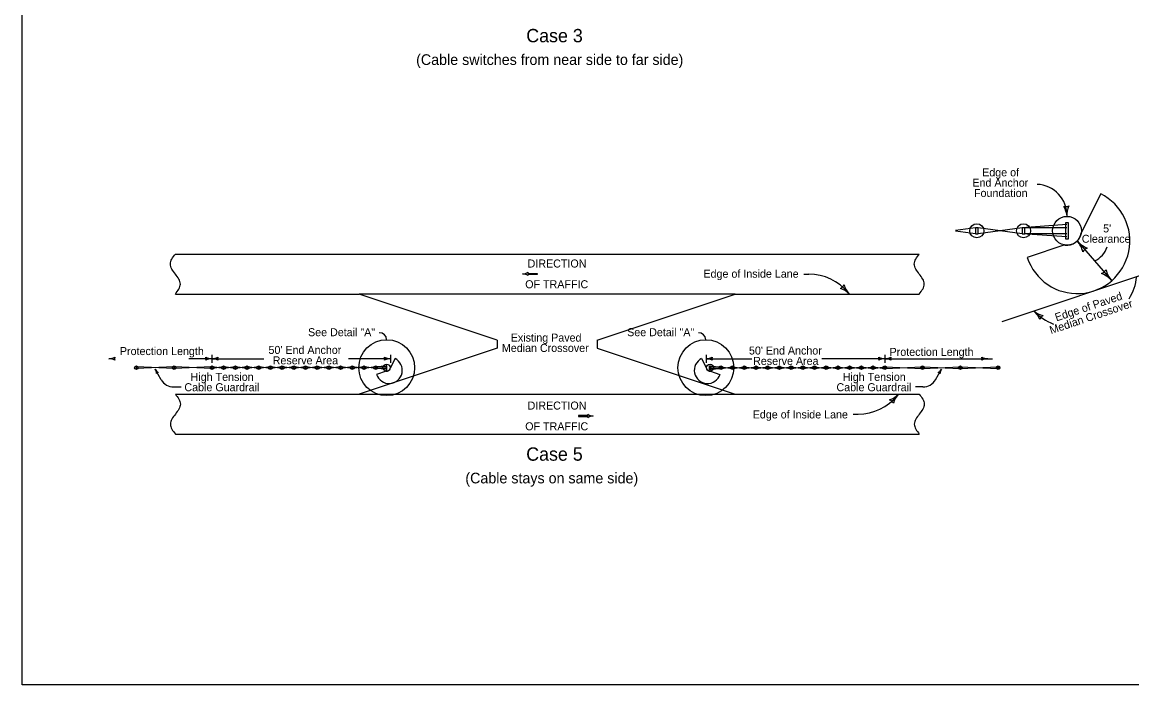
# Model space of a CAD drawing. Extents: x 10133 to 81668, y 7924 to 11018.
# Drawn here: x 10133 to 11797, y 7924 to 8918 of the extents above; entities that cross this region are included whole.
import ezdxf

# ---------------------------------------------------------------- set-up
doc = ezdxf.new("R2010")
doc.units = 0
for name, color, linetype in [('dsnCellElements', 7, 'Continuous'), ('DsnShtRevisedText', 7, 'Continuous'), ('dsnStdDimension', 7, 'Continuous'), ('Level 8', 7, 'Continuous'), ('SheetBorder', 7, 'Continuous')]:
    doc.layers.add(name, color=color, linetype=linetype)

msp = doc.modelspace()

# ---------------------------------------------------------------- linework, layer by layer
at = {"layer": 'dsnCellElements'}
for p, q in [((11562.3, 8609.3), (11532.3, 8605.3)), ((11562.3, 8600.3), (11532.3, 8604.4)), ((11632.4, 8609.3), (11566.1, 8600.3)), ((11632.4, 8600.3), (11566.1, 8609.3)), ((11699.4, 8614.1), (11632.4, 8609.3)), ((11699.4, 8609.3), (11636.1, 8609.3)), ((11699.4, 8595.6), (11632.4, 8600.3)), ((11699.4, 8600.3), (11636.1, 8600.3)), ((10359.9, 8400.6), (10304.1, 8398.3)), ((10359.9, 8398.3), (10304.1, 8400.6)), ((10416.6, 8400.6), (10360.8, 8398.3)), ((10416.6, 8398.3), (10360.8, 8400.6)), ((10434.2, 8400.6), (10417.5, 8398.3)), ((10434.2, 8398.3), (10417.5, 8400.6)), ((10451.7, 8400.6), (10435.1, 8398.3)), ((10451.7, 8398.3), (10435.1, 8400.6)), ((10469.3, 8400.6), (10452.6, 8398.3)), ((10469.3, 8398.3), (10452.6, 8400.6)), ((10486.8, 8400.6), (10470.2, 8398.3)), ((10486.8, 8398.3), (10470.2, 8400.6)), ((10504.3, 8400.6), (10487.7, 8398.3)), ((10504.3, 8398.3), (10487.7, 8400.6)), ((10521.9, 8400.6), (10505.3, 8398.3)), ((10521.9, 8398.3), (10505.3, 8400.6)), ((10539.4, 8400.6), (10522.8, 8398.3)), ((10539.4, 8398.3), (10522.8, 8400.6)), ((10557, 8398.3), (10540.4, 8400.6)), ((10557, 8400.6), (10540.4, 8398.3)), ((10574.5, 8400.6), (10557.9, 8398.3)), ((10574.5, 8398.3), (10557.9, 8400.6)), ((10592, 8400.6), (10575.5, 8398.3)), ((10592, 8398.3), (10575.5, 8400.6)), ((10609.6, 8400.6), (10593, 8398.3)), ((10609.6, 8398.3), (10593, 8400.6)), ((10627.2, 8400.6), (10610.6, 8398.3)), ((10627.2, 8398.3), (10610.6, 8400.6)), ((10644.7, 8400.6), (10628.1, 8398.3)), ((10644.7, 8398.3), (10628.1, 8400.6)), ((10662.3, 8400.6), (10645.7, 8398.3)), ((10662.3, 8398.3), (10645.7, 8400.6)), ((10679, 8401.8), (10662.3, 8400.6)), ((10679, 8397.2), (10662.3, 8398.3)), ((10679, 8400.6), (10663.2, 8400.6)), ((10679, 8398.3), (10663.2, 8398.3)), ((11164.1, 8401.8), (11180.9, 8400.6)), ((11164.1, 8400.6), (11179.9, 8400.6)), ((11164.1, 8398.3), (11179.9, 8398.3)), ((11164.1, 8397.2), (11180.9, 8398.3)), ((11180.9, 8400.6), (11197.5, 8398.3)), ((11180.9, 8398.3), (11197.5, 8400.6)), ((11198.4, 8400.6), (11215, 8398.3)), ((11198.4, 8398.3), (11215, 8400.6)), ((11216, 8400.6), (11232.6, 8398.3)), ((11216, 8398.3), (11232.6, 8400.6)), ((11233.5, 8400.6), (11250.1, 8398.3)), ((11233.5, 8398.3), (11250.1, 8400.6)), ((11251.1, 8400.6), (11267.7, 8398.3)), ((11251.1, 8398.3), (11267.7, 8400.6)), ((11268.6, 8400.6), (11285.2, 8398.3)), ((11268.6, 8398.3), (11285.2, 8400.6)), ((11286.2, 8398.3), (11302.8, 8400.6)), ((11286.2, 8400.6), (11302.8, 8398.3)), ((11303.7, 8400.6), (11320.3, 8398.3)), ((11303.7, 8398.3), (11320.3, 8400.6)), ((11321.3, 8400.6), (11337.8, 8398.3)), ((11321.3, 8398.3), (11337.8, 8400.6)), ((11338.8, 8400.6), (11355.4, 8398.3)), ((11338.8, 8398.3), (11355.4, 8400.6)), ((11356.3, 8400.6), (11372.9, 8398.3)), ((11356.3, 8398.3), (11372.9, 8400.6)), ((11373.9, 8400.6), (11390.5, 8398.3)), ((11373.9, 8398.3), (11390.5, 8400.6)), ((11391.4, 8400.6), (11408, 8398.3)), ((11391.4, 8398.3), (11408, 8400.6)), ((11409, 8400.6), (11425.6, 8398.3)), ((11409, 8398.3), (11425.6, 8400.6)), ((11426.5, 8400.6), (11482.3, 8398.3)), ((11426.5, 8398.3), (11482.3, 8400.6)), ((11483.2, 8400.6), (11539, 8398.3)), ((11483.2, 8398.3), (11539, 8400.6)), ((11539.9, 8400.6), (11595.7, 8398.3)), ((11539.9, 8398.3), (11595.7, 8400.6))]:
    msp.add_line(p, q, dxfattribs=at)
for points in [[(11566.1, 8600.3), (11566.1, 8609.3), (11562.3, 8609.3), (11562.3, 8600.3)], [(11636.2, 8600.3), (11636.2, 8609.3), (11632.4, 8609.3), (11632.4, 8600.3)], [(11701.9, 8592.8), (11701.9, 8616.9), (11697, 8616.9), (11697, 8592.8)], [(10304.1, 8398.3), (10304.1, 8400.6), (10303.2, 8400.6), (10303.2, 8398.3)], [(10360.8, 8398.3), (10360.8, 8400.6), (10359.9, 8400.6), (10359.9, 8398.3)], [(10360.8, 8398.3), (10360.8, 8400.6), (10359.9, 8400.6), (10359.9, 8398.3)], [(10417.5, 8398.3), (10417.5, 8400.6), (10416.6, 8400.6), (10416.6, 8398.3)], [(10417.5, 8398.3), (10417.5, 8400.6), (10416.6, 8400.6), (10416.6, 8398.3)], [(10435.1, 8398.3), (10435.1, 8400.6), (10434.2, 8400.6), (10434.2, 8398.3)], [(10452.6, 8398.3), (10452.6, 8400.6), (10451.7, 8400.6), (10451.7, 8398.3)], [(10470.2, 8398.3), (10470.2, 8400.6), (10469.3, 8400.6), (10469.3, 8398.3)], [(10487.7, 8398.3), (10487.7, 8400.6), (10486.8, 8400.6), (10486.8, 8398.3)], [(10505.3, 8398.3), (10505.3, 8400.6), (10504.3, 8400.6), (10504.3, 8398.3)], [(10522.8, 8398.3), (10522.8, 8400.6), (10521.9, 8400.6), (10521.9, 8398.3)], [(10540.4, 8398.3), (10540.4, 8400.6), (10539.4, 8400.6), (10539.4, 8398.3)], [(10557.9, 8398.3), (10557.9, 8400.6), (10557, 8400.6), (10557, 8398.3)], [(10575.5, 8398.3), (10575.5, 8400.6), (10574.5, 8400.6), (10574.5, 8398.3)], [(10593, 8398.3), (10593, 8400.6), (10592, 8400.6), (10592, 8398.3)], [(10610.6, 8398.3), (10610.6, 8400.6), (10609.6, 8400.6), (10609.6, 8398.3)], [(10628.1, 8398.3), (10628.1, 8400.6), (10627.2, 8400.6), (10627.2, 8398.3)], [(10645.7, 8398.3), (10645.7, 8400.6), (10644.7, 8400.6), (10644.7, 8398.3)], [(10663.2, 8398.3), (10663.2, 8400.6), (10662.3, 8400.6), (10662.3, 8398.3)], [(10679.6, 8396.5), (10679.6, 8402.5), (10678.4, 8402.5), (10678.4, 8396.5)], [(11163.5, 8396.5), (11163.5, 8402.5), (11164.7, 8402.5), (11164.7, 8396.5)], [(11179.9, 8398.3), (11179.9, 8400.6), (11180.9, 8400.6), (11180.9, 8398.3)], [(11197.5, 8398.3), (11197.5, 8400.6), (11198.4, 8400.6), (11198.4, 8398.3)], [(11215, 8398.3), (11215, 8400.6), (11216, 8400.6), (11216, 8398.3)], [(11232.6, 8398.3), (11232.6, 8400.6), (11233.5, 8400.6), (11233.5, 8398.3)], [(11250.1, 8398.3), (11250.1, 8400.6), (11251.1, 8400.6), (11251.1, 8398.3)], [(11267.7, 8398.3), (11267.7, 8400.6), (11268.6, 8400.6), (11268.6, 8398.3)], [(11285.2, 8398.3), (11285.2, 8400.6), (11286.2, 8400.6), (11286.2, 8398.3)], [(11302.8, 8398.3), (11302.8, 8400.6), (11303.7, 8400.6), (11303.7, 8398.3)], [(11320.3, 8398.3), (11320.3, 8400.6), (11321.3, 8400.6), (11321.3, 8398.3)], [(11337.8, 8398.3), (11337.8, 8400.6), (11338.8, 8400.6), (11338.8, 8398.3)], [(11355.4, 8398.3), (11355.4, 8400.6), (11356.3, 8400.6), (11356.3, 8398.3)], [(11372.9, 8398.3), (11372.9, 8400.6), (11373.9, 8400.6), (11373.9, 8398.3)], [(11390.5, 8398.3), (11390.5, 8400.6), (11391.4, 8400.6), (11391.4, 8398.3)], [(11408, 8398.3), (11408, 8400.6), (11409, 8400.6), (11409, 8398.3)], [(11425.6, 8398.3), (11425.6, 8400.6), (11426.5, 8400.6), (11426.5, 8398.3)], [(11425.6, 8398.3), (11425.6, 8400.6), (11426.5, 8400.6), (11426.5, 8398.3)], [(11482.3, 8398.3), (11482.3, 8400.6), (11483.2, 8400.6), (11483.2, 8398.3)], [(11482.3, 8398.3), (11482.3, 8400.6), (11483.2, 8400.6), (11483.2, 8398.3)], [(11539, 8398.3), (11539, 8400.6), (11539.9, 8400.6), (11539.9, 8398.3)], [(11539, 8398.3), (11539, 8400.6), (11539.9, 8400.6), (11539.9, 8398.3)], [(11595.7, 8398.3), (11595.7, 8400.6), (11596.6, 8400.6), (11596.6, 8398.3)]]:
    msp.add_lwpolyline(points, close=True, dxfattribs=at)
for centre, radius in [((11699.4, 8604.8), 21.6), ((11564.2, 8604.8), 10.6), ((11634.3, 8604.8), 10.6), ((10679, 8399.5), 5.4), ((11164.1, 8399.5), 5.4), ((10303.7, 8399.5), 2.66), ((10360.4, 8399.5), 2.66), ((10360.4, 8399.5), 2.66), ((10417.1, 8399.5), 2.66), ((10417.1, 8399.5), 2.66), ((10434.6, 8399.5), 2.66), ((10452.2, 8399.5), 2.66), ((10469.7, 8399.5), 2.66), ((10487.2, 8399.5), 2.66), ((10504.8, 8399.5), 2.66), ((10522.3, 8399.5), 2.66), ((10539.9, 8399.5), 2.66), ((10557.4, 8399.5), 2.66), ((10575, 8399.5), 2.66), ((10592.5, 8399.5), 2.66), ((10610.1, 8399.5), 2.66), ((10627.6, 8399.5), 2.66), ((10645.2, 8399.5), 2.66), ((10662.7, 8399.5), 2.66), ((11180.4, 8399.5), 2.66), ((11197.9, 8399.5), 2.66), ((11215.5, 8399.5), 2.66), ((11233, 8399.5), 2.66), ((11250.6, 8399.5), 2.66), ((11268.1, 8399.5), 2.66), ((11285.7, 8399.5), 2.66), ((11303.2, 8399.5), 2.66), ((11320.8, 8399.5), 2.66), ((11338.3, 8399.5), 2.66), ((11355.9, 8399.5), 2.66), ((11373.4, 8399.5), 2.66), ((11391, 8399.5), 2.66), ((11408.5, 8399.5), 2.66), ((11426.1, 8399.5), 2.66), ((11426.1, 8399.5), 2.66), ((11482.8, 8399.5), 2.66), ((11482.8, 8399.5), 2.66), ((11539.5, 8399.5), 2.66), ((11539.5, 8399.5), 2.66), ((11596.2, 8399.5), 2.66)]:
    msp.add_circle(centre, radius, dxfattribs=at)
at = {"layer": 'DsnShtRevisedText'}
for p, q in [((11750.1, 8660.3), (11720.8, 8601.8)), ((11750.1, 8660.3), (11720.8, 8601.8)), ((11714.7, 8589.6), (11766.5, 8529.9)), ((11696.4, 8583.5), (11639.7, 8564.6)), ((11696.4, 8583.5), (11639.7, 8564.6)), ((11602.1, 8468.7), (11860.1, 8554.7)), ((10883, 8540.1), (10883, 8540.1)), ((10891, 8542.6), (10891, 8540.8)), ((10891, 8540.8), (10905, 8540.8)), ((10905, 8539.3), (10891, 8539.3)), ((10891, 8539.3), (10891, 8537.5)), ((10905, 8540.8), (10905, 8539.3)), ((11304.7, 8539.7), (11312.2, 8539.7)), ((10417, 8413), (10382.5, 8413)), ((10417, 8419), (10417, 8407)), ((10417, 8413), (10494.9, 8413)), ((10685.1, 8413), (10621.7, 8413)), ((10691.7, 8413.3), (10684.4, 8398.7)), ((10691.7, 8413.3), (10684.4, 8398.7)), ((10685.1, 8419), (10685.1, 8407)), ((11151.5, 8413.3), (11158.8, 8398.7)), ((11151.5, 8413.3), (11158.8, 8398.7)), ((11158.1, 8419), (11158.1, 8407)), ((11158.1, 8413), (11226.8, 8413)), ((11426.2, 8413), (11331.8, 8413)), ((11426.2, 8419), (11426.2, 8407)), ((11426.2, 8413), (11535.6, 8413)), ((11535.6, 8413), (11587.9, 8413)), ((10340.9, 8381.5), (10332, 8397.1)), ((10678.2, 8394.1), (10664.1, 8389.4)), ((10678.2, 8394.1), (10664.1, 8389.4)), ((11164.9, 8394.1), (11179, 8389.4)), ((11164.9, 8394.1), (11179, 8389.4)), ((11502.2, 8381.5), (11511.1, 8397.1)), ((10359.7, 8370.6), (10371, 8370.6)), ((11483.4, 8370.6), (11472.1, 8370.6)), ((10980.9, 8327.8), (10966.9, 8327.8)), ((10966.9, 8327.8), (10966.9, 8326.3)), ((10966.9, 8326.3), (10980.9, 8326.3)), ((10980.9, 8329.6), (10980.9, 8327.8)), ((10980.9, 8326.3), (10980.9, 8324.5)), ((10989, 8327.1), (10989, 8327.1)), ((11378.6, 8330), (11386.1, 8330))]:
    msp.add_line(p, q, dxfattribs=at)
for centre in [(10679.2, 8399.5), (11157.8, 8399.5)]:
    msp.add_circle(centre, 41.9, dxfattribs=at)
for centre, radius, start, end in [((11653, 8627.9), 46.5, 358.2185, 88.2185), ((11714.7, 8589.6), 79, 198.4349, 63.4349), ((11714.7, 8589.6), 79, 198.4349, 63.4349), ((11697.3, 8653.5), 12.5, 256.782, 292.2487), ((11667.2, 8623.9), 32.4, 4.5153, 32.5878), ((11731.7, 8629), 32.4, 156.4428, 184.5153), ((11699.4, 8604.8), 21.6, 261.8699, 351.8699), ((11699.4, 8604.8), 21.6, 261.8699, 351.8699), ((11685.8, 8564.5), 38.3, 12.8625, 40.935), ((11743.6, 8614.6), 38.3, 220.935, 249.0074), ((11735.7, 8565.3), 14.8, 113.2016, 148.6683), ((11728.3, 8589.9), 32.6, 292.2406, 343.2299), ((10882.3, 8556.4), 16.4, 272.352, 302.382), ((10882.3, 8523.7), 16.4, 57.618, 87.648), ((11312.2, 8463.6), 76.2, 39.0106, 90), ((11745.5, 8554.1), 14.8, 293.2016, 328.6683), ((11737.6, 8504.8), 38.3, 40.935, 69.0074), ((11795.4, 8554.9), 38.3, 192.8625, 220.935), ((11354.2, 8529.7), 12.5, 295.2639, 330.7306), ((11396.4, 8532), 32.4, 194.9248, 222.9973), ((11724.4, 8544.9), 80.1, 328.1378, 353.6325), ((11349, 8487.8), 32.4, 42.9973, 71.0698), ((11670.5, 8509.3), 32.4, 229.8905, 257.9629), ((11628.8, 8459.8), 32.4, 21.818, 49.8905), ((11708.1, 8539.5), 80.1, 223.2374, 248.7321), ((11670.4, 8467.1), 12.5, 122.1571, 157.6238), ((10668.3, 8441.1), 10.8, 1.4994, 91.4994), ((11147, 8441.1), 10.8, 1.4994, 91.4994), ((10262.5, 8432.1), 19.1, 270, 298.0725), ((10262.5, 8393.9), 19.1, 61.9275, 90), ((10278.5, 8413), 7.39, 162.2666, 197.7334), ((10400.9, 8413), 7.39, 342.2666, 17.7333), ((10417, 8432.1), 19.1, 241.9275, 270), ((10417, 8393.9), 19.1, 90, 118.0725), ((10417, 8432.1), 19.1, 270, 298.0725), ((10417, 8393.9), 19.1, 61.9275, 90), ((10433, 8413), 7.39, 162.2666, 197.7334), ((10682.8, 8395.6), 19.8, 198.4349, 63.4349), ((10682.8, 8395.6), 19.8, 198.4349, 63.4349), ((10669, 8413), 7.39, 342.2667, 17.7334), ((10685.1, 8432.1), 19.1, 241.9275, 270), ((10685.1, 8393.9), 19.1, 90, 118.0725), ((11160.3, 8395.6), 19.8, 116.5651, 341.5651), ((11160.3, 8395.6), 19.8, 116.5651, 341.5651), ((11158.1, 8432.1), 19.1, 270, 298.0725), ((11158.1, 8393.9), 19.1, 61.9275, 90), ((11174.1, 8413), 7.39, 162.2666, 197.7334), ((11410.1, 8413), 7.39, 342.2667, 17.7334), ((11426.2, 8432.1), 19.1, 241.9275, 270), ((11426.2, 8393.9), 19.1, 90, 118.0725), ((11426.2, 8432.1), 19.1, 270, 298.0725), ((11426.2, 8393.9), 19.1, 61.9275, 90), ((11442.2, 8413), 7.39, 162.2666, 197.7334), ((11564.6, 8413), 7.39, 342.2666, 17.7333), ((11580.6, 8432.1), 19.1, 241.9275, 270), ((11580.6, 8393.9), 19.1, 90, 118.0725), ((10320.3, 8390.3), 13.6, 2.1589, 30.2314), ((10343.8, 8404), 13.6, 210.2314, 238.3038), ((10337.8, 8387.3), 5.25, 102.498, 137.9647), ((10679, 8399.5), 5.4, 261.8699, 351.8699), ((10679, 8399.5), 5.4, 261.8699, 351.8699), ((11164.1, 8399.5), 5.4, 188.1301, 278.1301), ((11164.1, 8399.5), 5.4, 188.1301, 278.1301), ((11499.3, 8404), 13.6, 301.6962, 329.7686), ((11505.3, 8387.3), 5.25, 42.0353, 77.502), ((11522.8, 8390.3), 13.6, 149.7686, 177.8411), ((10359.7, 8392.4), 21.8, 210.2243, 270), ((11483.4, 8392.4), 21.8, 270, 329.7757), ((11386.1, 8406.2), 76.2, 270, 320.9894), ((11422.9, 8382), 32.4, 288.9302, 317.0027), ((11470.3, 8337.8), 32.4, 137.0027, 165.0752), ((11428.1, 8340), 12.5, 29.2694, 64.7361), ((10989.7, 8343.4), 16.4, 237.618, 267.648), ((10989.7, 8310.7), 16.4, 92.352, 122.382)]:
    msp.add_arc(centre, radius, start, end, dxfattribs=at)
at = {"layer": 'dsnStdDimension'}
for p, q in [((10362.2, 8569.9), (11477.9, 8569.9)), ((10362.2, 8509.9), (10638, 8509.9)), ((10845, 8440.9), (10638, 8509.9)), ((11202, 8509.9), (10638, 8509.9)), ((10995, 8440.9), (11202, 8509.9)), ((11198.9, 8509.9), (11477.9, 8509.9)), ((10845, 8440.9), (10845, 8428.9)), ((10995, 8440.9), (10995, 8428.9)), ((10845, 8428.9), (10638, 8359.9)), ((10995, 8428.9), (11202, 8359.9)), ((10362.2, 8359.9), (10641.1, 8359.9)), ((10641.1, 8359.9), (11202, 8359.9)), ((11202, 8359.9), (11477.9, 8359.9)), ((10362.2, 8299.9), (11477.9, 8299.9))]:
    msp.add_line(p, q, dxfattribs=at)
for points in [[(10362.2, 8509.9), (10369.7, 8524.9), (10362.2, 8539.9), (10354.7, 8554.9), (10362.2, 8569.9)], [(11477.9, 8509.9), (11485.4, 8524.9), (11477.9, 8539.9), (11470.4, 8554.9), (11477.9, 8569.9)], [(10362.2, 8359.9), (10369.7, 8344.9), (10362.2, 8329.9), (10354.7, 8314.9), (10362.2, 8299.9)], [(11477.9, 8359.9), (11485.4, 8344.9), (11477.9, 8329.9), (11470.4, 8314.9), (11477.9, 8299.9)]]:
    msp.add_spline(points, degree=3, dxfattribs=at)
at = {"layer": 'SheetBorder'}
msp.add_lwpolyline([(10132.5, 9944), (13267.5, 9944), (13267.5, 7924), (10132.5, 7924)], close=True, dxfattribs=at)

# ---------------------------------------------------------------- texts
at = {"layer": 'DsnShtRevisedText'}
for s, p in [('Edge of ', (11572.2, 8686.4)), ('End Anchor', (11557.5, 8670.9)), ('Foundation', (11560, 8655.4)), ("5'", (11753.6, 8602.3)), ('Clearance', (11721.6, 8586.8)), ('DIRECTION', (10890.5, 8549.7)), ('Edge of Inside Lane', (11154.2, 8534.4)), ('OF TRAFFIC', (10886.9, 8518.6)), ('See Detail "A"', (10561.2, 8446.7)), ('See Detail "A"', (11039.8, 8446.7)), ('Existing Paved', (10865.2, 8438.6)), ('Protection Length', (10279.1, 8418.4)), ("50' End Anchor", (10501.9, 8420.1)), ('Median Crossover', (10851.9, 8423.1)), ("50' End Anchor", (11222.5, 8419.2)), ('Protection Length', (11433.4, 8417.2)), ('Reserve Area', (10508.2, 8404.5)), ('Reserve Area', (11228.7, 8403.6)), ('High Tension', (10385.1, 8379.7)), ('High Tension', (11363, 8379.7)), ('Cable Guardrail', (10375.8, 8364.2)), ('Cable Guardrail', (11353.7, 8364.2)), ('DIRECTION', (10890.5, 8336.7)), ('Edge of Inside Lane', (11228.1, 8323.4)), ('OF TRAFFIC', (10886.9, 8305.6))]:
    msp.add_text(s, height=12, dxfattribs=at).set_placement(p)
for s, p in [('Edge of Paved', (11683.6, 8468.8)), ('Median Crossover', (11675.5, 8449.7))]:
    msp.add_text(s, height=12, rotation=18.4349, dxfattribs=at).set_placement(p)
at = {"layer": 'Level 8'}
for s, height, p in [('Case 3', 20, (10888.5, 8887.4)), ('(Cable switches from near side to far side)', 16, (10723.3, 8853.4)), ('Case 5', 20, (10888.4, 8260)), ('(Cable stays on same side)', 16, (10797.1, 8226))]:
    msp.add_text(s, height=height, dxfattribs=at).set_placement(p)

doc.saveas('drawing.dxf')
